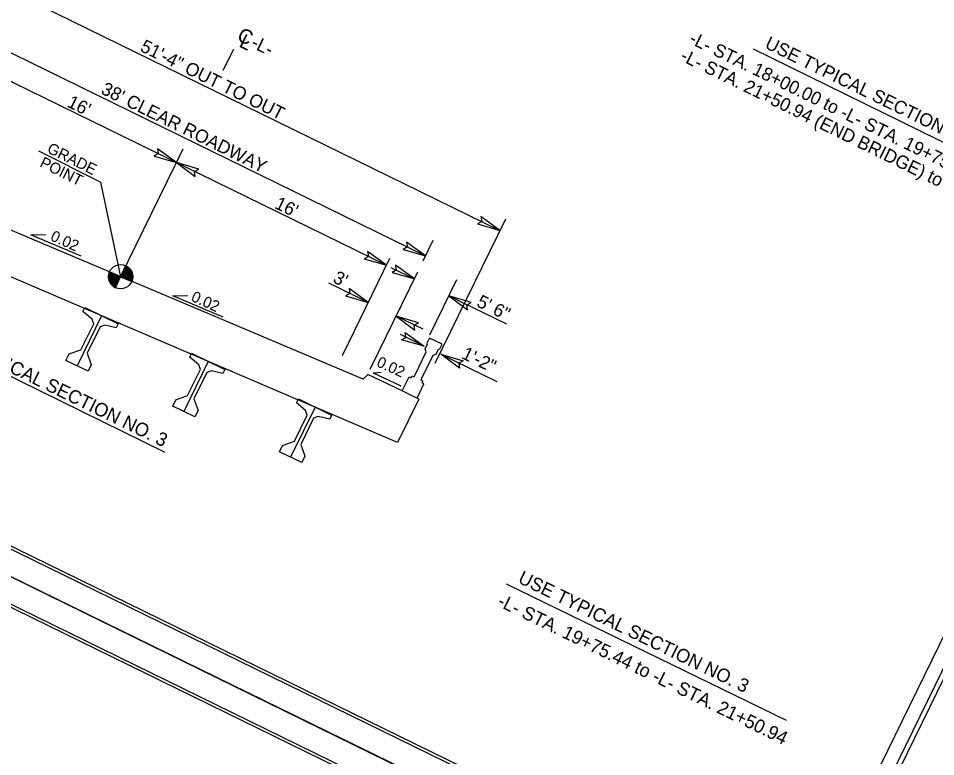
# Model space of a CAD drawing. Extents: x 1518247 to 1523638, y 635234 to 639927.
# Drawn here: x 1521243 to 1522074, y 637399 to 638068 of the extents above; entities that cross this region are included whole.
import ezdxf

# ---------------------------------------------------------------- set-up
doc = ezdxf.new("R2010")
doc.units = 0
for name, color, linetype in [('Default', 7, 'Continuous'), ('Default Symbol CELL', 7, 'Continuous'), ('Old_Level_1', 7, 'Continuous'), ('Prop Conc Barrier', 7, 'Continuous'), ('Prop Dimension', 7, 'Continuous'), ('Prop Dimension Text', 7, 'Continuous'), ('Sheet Cutting Line CELL', 7, 'Continuous'), ('Sheet Plot Border Inside CELL', 7, 'Continuous'), ('Sheet Plot Border Outside CELL', 7, 'Continuous'), ('Sheet Typical CELL', 7, 'Continuous'), ('Typical Arrow Superelevation CELL', 7, 'Continuous'), ('Typical Berm Information CELL', 7, 'Continuous'), ('Typical Pavement Slope CELL', 7, 'Continuous'), ('Typical Sidewalk and Rail CELL', 7, 'Continuous'), ('Typical Text Centerline CELL', 7, 'Continuous'), ('Typical Text Label CELL', 7, 'Continuous')]:
    doc.layers.add(name, color=color, linetype=linetype)

msp = doc.modelspace()

# ---------------------------------------------------------------- linework, layer by layer
at = {"layer": 'Default'}
for points in [[(1520441.97, 637950.34), (1521954.73, 637210.48), (1522438.02, 638198.63), (1520925.25, 638938.49)], [(1521471.45, 636222.33), (1519958.68, 636962.19), (1520441.97, 637950.34), (1521954.73, 637210.48)]]:
    msp.add_lwpolyline(points, close=True, dxfattribs=at)
at = {"layer": 'Default Symbol CELL'}
for p, q in [((1521301.17, 637802.23), (1521302.93, 637805.82)), ((1521302.93, 637805.82), (1521333.09, 637791.07)), ((1521318.01, 637798.44), (1521295.87, 637753.17)), ((1521309.46, 637795.51), (1521301.17, 637802.23)), ((1521299.32, 637767.51), (1521310.92, 637791.23)), ((1521316.67, 637788.42), (1521305.08, 637764.72)), ((1521310.92, 637791.23), (1521309.46, 637795.51)), ((1521320.95, 637789.89), (1521316.67, 637788.42)), ((1521331.34, 637787.48), (1521320.95, 637789.89)), ((1521333.09, 637791.07), (1521331.34, 637787.48)), ((1521285.82, 637758.09), (1521288.63, 637763.84)), ((1521288.63, 637763.84), (1521299.32, 637767.51)), ((1521305.07, 637764.7), (1521308.74, 637754)), ((1521397.94, 637760.86), (1521399.7, 637764.45)), ((1521399.7, 637764.45), (1521429.86, 637749.69)), ((1521305.93, 637748.26), (1521285.82, 637758.09)), ((1521414.78, 637757.07), (1521392.64, 637711.8)), ((1521406.22, 637754.14), (1521397.94, 637760.86)), ((1521308.74, 637754), (1521305.93, 637748.26)), ((1521396.09, 637726.14), (1521407.69, 637749.86)), ((1521413.44, 637747.05), (1521401.84, 637723.35)), ((1521407.69, 637749.86), (1521406.22, 637754.14)), ((1521417.71, 637748.52), (1521413.44, 637747.05)), ((1521428.1, 637746.1), (1521417.71, 637748.52)), ((1521429.86, 637749.69), (1521428.1, 637746.1)), ((1521382.58, 637716.72), (1521385.39, 637722.47)), ((1521385.39, 637722.47), (1521396.09, 637726.14)), ((1521401.83, 637723.33), (1521405.5, 637712.63)), ((1521494.71, 637719.48), (1521496.46, 637723.08)), ((1521496.46, 637723.08), (1521526.63, 637708.32)), ((1521402.69, 637706.89), (1521382.58, 637716.72)), ((1521511.55, 637715.7), (1521489.41, 637670.43)), ((1521502.99, 637712.76), (1521494.71, 637719.48)), ((1521405.5, 637712.63), (1521402.69, 637706.89)), ((1521492.86, 637684.76), (1521504.46, 637708.49)), ((1521510.2, 637705.68), (1521498.61, 637681.98)), ((1521504.46, 637708.49), (1521502.99, 637712.76)), ((1521514.48, 637707.14), (1521510.2, 637705.68)), ((1521524.87, 637704.73), (1521514.48, 637707.14)), ((1521526.63, 637708.32), (1521524.87, 637704.73)), ((1521479.35, 637675.35), (1521482.16, 637681.09)), ((1521482.16, 637681.09), (1521492.86, 637684.76)), ((1521498.6, 637681.95), (1521502.27, 637671.26)), ((1521499.46, 637665.51), (1521479.35, 637675.35)), ((1521502.27, 637671.26), (1521499.46, 637665.51))]:
    msp.add_line(p, q, dxfattribs=at)
at = {"layer": 'Old_Level_1'}
for p, q in [((1521437.59, 638039.67), (1521428.12, 638020.64)), ((1521316.96, 637919.46), (1521261.28, 637947.56)), ((1521335.32, 637833.84), (1521391.91, 637949.54)), ((1521555.19, 637741.09), (1521125.64, 637922.33)), ((1521316.96, 637919.46), (1521335.32, 637833.84)), ((1521586.4, 637683.7), (1521058.69, 637909.31)), ((1521253.86, 637871.76), (1521267.53, 637871.94)), ((1521299.57, 637852.39), (1521253.86, 637871.76)), ((1521325.28, 637838.3), (1521335.32, 637833.84)), ((1521335.32, 637833.84), (1521325.28, 637838.3)), ((1521339.81, 637843.88), (1521335.32, 637833.84)), ((1521330.84, 637823.81), (1521335.32, 637833.84)), ((1521335.32, 637833.84), (1521345.36, 637829.36)), ((1521382.68, 637816.63), (1521396.35, 637816.8)), ((1521428.39, 637797.25), (1521382.68, 637816.63))]:
    msp.add_line(p, q, dxfattribs=at)
for points in [[(1521365.61, 637943.16), (1521385.95, 637937.35), (1521368.67, 637949.78), (1521369.46, 637945.29)], [(1521406.21, 637931.28), (1521385.95, 637937.35), (1521403.06, 637924.7), (1521402.33, 637929.2)], [(1521658.8, 637881.6), (1521679.14, 637875.79), (1521661.86, 637888.22), (1521662.65, 637883.73)], [(1521591.38, 637858.62), (1521611.71, 637852.82), (1521594.43, 637865.25), (1521595.23, 637860.75)], [(1521556.05, 637850.02), (1521576.39, 637844.21), (1521559.11, 637856.64), (1521559.9, 637852.15)], [(1521581.4, 637837.62), (1521601.74, 637831.82), (1521584.45, 637844.25), (1521585.25, 637839.75)], [(1521539.31, 637816.39), (1521559.65, 637810.58), (1521542.37, 637823.01), (1521543.16, 637818.52)], [(1521653.06, 637810.55), (1521632.8, 637816.62), (1521649.91, 637803.96), (1521649.18, 637808.47)], [(1521605.25, 637792.11), (1521585, 637798.19), (1521602.11, 637785.53), (1521601.37, 637790.03)], [(1521593.23, 637783.2), (1521610.46, 637770.94), (1521589.96, 637776.68), (1521593.97, 637778.86)], [(1521642.55, 637751.11), (1521625.48, 637763.6), (1521645.9, 637757.59), (1521641.86, 637755.45)]]:
    msp.add_lwpolyline(points, close=True, dxfattribs=at)
for points in [[(1521335.25, 637833.69), (1521325.22, 637838.17), (1521325.22, 637838.17)], [(1521346.3, 637834.1), (1521337.25, 637838.15)], [(1521346.3, 637834.34), (1521337.34, 637838.35)], [(1521346.28, 637834.59), (1521337.43, 637838.55)], [(1521346.26, 637834.84), (1521337.52, 637838.75)], [(1521346.24, 637835.09), (1521337.61, 637838.95)], [(1521346.21, 637835.34), (1521337.69, 637839.15)], [(1521346.17, 637835.6), (1521337.78, 637839.35)], [(1521346.13, 637835.86), (1521337.87, 637839.55)], [(1521346.06, 637836.13), (1521337.96, 637839.75)], [(1521346.02, 637836.39), (1521338.05, 637839.95)], [(1521345.95, 637836.66), (1521338.14, 637840.15)], [(1521345.86, 637836.95), (1521338.23, 637840.35)], [(1521345.77, 637837.23), (1521338.32, 637840.55)], [(1521345.68, 637837.51), (1521338.41, 637840.75)], [(1521345.57, 637837.8), (1521338.5, 637840.96)], [(1521345.46, 637838.09), (1521338.59, 637841.16)], [(1521345.33, 637838.39), (1521338.68, 637841.36)], [(1521345.17, 637838.7), (1521338.77, 637841.56)], [(1521345.02, 637839.01), (1521338.86, 637841.76)], [(1521344.84, 637839.33), (1521338.95, 637841.96)], [(1521344.64, 637839.66), (1521339.04, 637842.16)], [(1521344.42, 637840), (1521339.13, 637842.36)], [(1521344.17, 637840.35), (1521339.22, 637842.56)], [(1521343.9, 637840.71), (1521339.31, 637842.76)], [(1521343.57, 637841.1), (1521339.4, 637842.96)], [(1521343.19, 637841.51), (1521339.49, 637843.16)], [(1521342.72, 637841.96), (1521339.58, 637843.36)], [(1521342.12, 637842.47), (1521339.67, 637843.57)], [(1521341.19, 637843.13), (1521339.76, 637843.77)], [(1521333.73, 637830.27), (1521324.34, 637834.47)], [(1521333.64, 637830.07), (1521324.34, 637834.23)], [(1521333.55, 637829.87), (1521324.34, 637833.99)], [(1521333.46, 637829.67), (1521324.34, 637833.75)], [(1521333.37, 637829.47), (1521324.34, 637833.51)], [(1521333.28, 637829.27), (1521324.34, 637833.27)], [(1521333.82, 637830.47), (1521324.36, 637834.7)], [(1521333.19, 637829.07), (1521324.36, 637833.02)], [(1521333.91, 637830.67), (1521324.38, 637834.93)], [(1521333.1, 637828.87), (1521324.38, 637832.76)], [(1521333.01, 637828.67), (1521324.4, 637832.51)], [(1521334, 637830.88), (1521324.41, 637835.16)], [(1521334.09, 637831.08), (1521324.45, 637835.38)], [(1521332.92, 637828.47), (1521324.45, 637832.25)], [(1521334.18, 637831.28), (1521324.48, 637835.61)], [(1521332.83, 637828.27), (1521324.49, 637831.99)], [(1521334.27, 637831.48), (1521324.52, 637835.83)], [(1521332.74, 637828.06), (1521324.53, 637831.73)], [(1521334.36, 637831.68), (1521324.57, 637836.05)], [(1521332.65, 637827.86), (1521324.58, 637831.47)], [(1521334.45, 637831.88), (1521324.61, 637836.27)], [(1521332.56, 637827.66), (1521324.65, 637831.2)], [(1521334.54, 637832.08), (1521324.66, 637836.49)], [(1521332.47, 637827.46), (1521324.71, 637830.93)], [(1521334.63, 637832.28), (1521324.72, 637836.71)], [(1521334.72, 637832.48), (1521324.77, 637836.93)], [(1521332.38, 637827.26), (1521324.8, 637830.65)], [(1521334.8, 637832.68), (1521324.84, 637837.14)], [(1521332.29, 637827.06), (1521324.89, 637830.37)], [(1521334.89, 637832.88), (1521324.9, 637837.35)], [(1521334.98, 637833.08), (1521324.97, 637837.56)], [(1521332.2, 637826.86), (1521324.98, 637830.09)], [(1521335.07, 637833.28), (1521325.06, 637837.76)], [(1521332.11, 637826.66), (1521325.09, 637829.8)], [(1521335.16, 637833.48), (1521325.13, 637837.97)], [(1521345.4, 637829.45), (1521345.4, 637829.45), (1521335.36, 637833.93)], [(1521345.49, 637829.65), (1521335.45, 637834.13)], [(1521345.56, 637829.86), (1521335.54, 637834.33)], [(1521345.65, 637830.06), (1521335.63, 637834.53)], [(1521345.71, 637830.27), (1521335.72, 637834.73)], [(1521345.78, 637830.48), (1521335.81, 637834.93)], [(1521345.85, 637830.69), (1521335.9, 637835.13)], [(1521345.91, 637830.9), (1521335.99, 637835.34)], [(1521345.98, 637831.11), (1521336.08, 637835.54)], [(1521346.03, 637831.33), (1521336.17, 637835.74)], [(1521346.07, 637831.55), (1521336.26, 637835.94)], [(1521346.12, 637831.77), (1521336.35, 637836.14)], [(1521346.16, 637831.99), (1521336.44, 637836.34)], [(1521346.19, 637832.22), (1521336.53, 637836.54)], [(1521346.23, 637832.45), (1521336.62, 637836.74)], [(1521346.25, 637832.68), (1521336.71, 637836.94)], [(1521346.28, 637832.91), (1521336.8, 637837.14)], [(1521346.3, 637833.14), (1521336.89, 637837.34)], [(1521346.3, 637833.38), (1521336.98, 637837.54)], [(1521346.3, 637833.62), (1521337.07, 637837.74)], [(1521346.3, 637833.86), (1521337.16, 637837.94)], [(1521332.02, 637826.46), (1521325.22, 637829.5)], [(1521331.93, 637826.26), (1521325.36, 637829.2)], [(1521331.84, 637826.06), (1521325.51, 637828.89)], [(1521331.76, 637825.86), (1521325.67, 637828.58)], [(1521331.67, 637825.66), (1521325.84, 637828.26)], [(1521331.58, 637825.46), (1521326.05, 637827.93)], [(1521331.49, 637825.26), (1521326.27, 637827.59)], [(1521331.4, 637825.05), (1521326.53, 637827.23)], [(1521331.31, 637824.85), (1521326.82, 637826.86)], [(1521331.22, 637824.65), (1521327.16, 637826.47)], [(1521331.13, 637824.45), (1521327.54, 637826.06)], [(1521331.04, 637824.25), (1521328.05, 637825.59)], [(1521330.95, 637824.05), (1521328.67, 637825.07)], [(1521330.86, 637823.85), (1521329.77, 637824.34)]]:
    msp.add_lwpolyline(points, dxfattribs=at)
msp.add_circle((1521335.32, 637833.83), 10.99, dxfattribs=at)
for start, end in [(155.93113, 245.93113), (335.93113, 65.93113)]:
    msp.add_arc((1521335.32, 637833.83), 10.99, start, end, dxfattribs=at)
at = {"layer": 'Prop Conc Barrier'}
for p, q in [((1521611.47, 637768.55), (1521613.65, 637773.01)), ((1521613.14, 637774), (1521615.25, 637778.3)), ((1521613.65, 637773.01), (1521613.14, 637774)), ((1521626.74, 637772.68), (1521615.25, 637778.3)), ((1521624.63, 637768.38), (1521626.74, 637772.68)), ((1521602.24, 637745.08), (1521612.44, 637765.94)), ((1521612.44, 637765.94), (1521611.47, 637768.55)), ((1521618.72, 637762.9), (1521621.34, 637763.72)), ((1521621.34, 637763.72), (1521623.51, 637768.17)), ((1521623.51, 637768.17), (1521624.63, 637768.38)), ((1521608.51, 637742.02), (1521618.72, 637762.9)), ((1521590.63, 637730.4), (1521596.92, 637743.26)), ((1521596.92, 637743.26), (1521598.71, 637742.39)), ((1521598.71, 637742.39), (1521599.58, 637744.17)), ((1521599.58, 637744.17), (1521601.37, 637743.3)), ((1521601.37, 637743.3), (1521602.24, 637745.08)), ((1521607.63, 637740.23), (1521608.51, 637742.02)), ((1521609.42, 637739.36), (1521607.63, 637740.23)), ((1521608.54, 637737.58), (1521609.42, 637739.36)), ((1521605.65, 637723.06), (1521590.63, 637730.4)), ((1521604.04, 637723.85), (1521610.33, 637736.7)), ((1521610.33, 637736.7), (1521608.54, 637737.58))]:
    msp.add_line(p, q, dxfattribs=at)
at = {"layer": 'Prop Dimension'}
for p, q in [((1521165.23, 638127.14), (1521679.14, 637875.79)), ((1521189.36, 638059.38), (1521611.71, 637852.82)), ((1521204.65, 638026.02), (1521576.23, 637844.29)), ((1521684.12, 637885.96), (1521620.18, 637755.24)), ((1521609.46, 637848.21), (1521618.67, 637867.04)), ((1521536.38, 637762.39), (1521579.49, 637850.55)), ((1521561.48, 637750.11), (1521604.6, 637838.27)), ((1521580.4, 637842.25), (1521601.74, 637831.82)), ((1521639.89, 637831.11), (1521615.32, 637780.87)), ((1521559.89, 637810.47), (1521524.16, 637827.94)), ((1521632.8, 637816.62), (1521685, 637791.09)), ((1521609.53, 637786.19), (1521585, 637798.19)), ((1521610.46, 637770.94), (1521589.18, 637781.35)), ((1521625.48, 637763.6), (1521676.22, 637738.78))]:
    msp.add_line(p, q, dxfattribs=at)
at = {"layer": 'Sheet Cutting Line CELL'}
for p, q in [((1520441.97, 637950.34), (1521954.73, 637210.48)), ((1521954.73, 637210.48), (1520441.97, 637950.34))]:
    msp.add_line(p, q, dxfattribs=at)
at = {"layer": 'Sheet Plot Border Inside CELL'}
for points in [[(1522424.11, 638180.44), (1520927.06, 638912.61), (1520463.51, 637964.8), (1521960.55, 637232.62)], [(1521940.83, 637192.29), (1520443.78, 637924.46), (1519980.23, 636976.65), (1521477.27, 636244.48)]]:
    msp.add_lwpolyline(points, close=True, dxfattribs=at)
at = {"layer": 'Sheet Plot Border Outside CELL'}
for points in [[(1522438.02, 638198.63), (1520925.25, 638938.49), (1520441.97, 637950.34), (1521954.73, 637210.48)], [(1521954.73, 637210.48), (1520441.97, 637950.34), (1519958.68, 636962.19), (1521471.45, 636222.33)]]:
    msp.add_lwpolyline(points, close=True, dxfattribs=at)
at = {"layer": 'Sheet Typical CELL'}
for points in [[(1522411.76, 638183.64), (1521064.29, 638842.66), (1520602.97, 637899.43), (1521950.45, 637240.41)], [(1521928.48, 637195.49), (1520581, 637854.51), (1520119.69, 636911.28), (1521467.16, 636252.26)]]:
    msp.add_lwpolyline(points, close=True, dxfattribs=at)
at = {"layer": 'Typical Arrow Superelevation CELL'}
msp.add_line((1521564.26, 637746.8), (1521571.52, 637747.44), dxfattribs=at)
at = {"layer": 'Typical Berm Information CELL'}
msp.add_line((1521564.26, 637746.8), (1521589.44, 637735.1), dxfattribs=at)
at = {"layer": 'Typical Sidewalk and Rail CELL'}
for p, q in [((1521555.19, 637741.09), (1521559.31, 637745.38)), ((1521590.63, 637730.4), (1521559.31, 637745.38)), ((1521605.65, 637723.06), (1521586.4, 637683.7))]:
    msp.add_line(p, q, dxfattribs=at)
at = {"layer": 'Typical Text Label CELL'}
for p, q in [((1521908.73, 638040.14), (1522156.85, 637918.56)), ((1521193.4, 637764.17), (1521375.3, 637675.05)), ((1521684.76, 637555.82), (1521938.76, 637432.21))]:
    msp.add_line(p, q, dxfattribs=at)

# ---------------------------------------------------------------- texts
at = {"layer": 'Old_Level_1'}
for s, height, rotation, p in [('GRADE', 10.005, 333.53399, (1521267.9, 637946.81)), ('POINT', 10.005, 333.53399, (1521261.25, 637933.97)), ('0.02', 9.969, 335.9216, (1521271.02, 637867.09)), ('0.02', 9.969, 335.9216, (1521398.51, 637812.18))]:
    msp.add_text(s, height=height, rotation=rotation, dxfattribs=at).set_placement(p)
at = {"layer": 'Prop Dimension'}
for s, height, rotation, p in [('51\'-4" OUT TO OUT', 11.8652, 333.74084, (1521352.24, 638038.61)), ("38' CLEAR ROADWAY", 11.8652, 333.74084, (1521316.71, 638000.12)), ("16'", 11.865, 333.74084, (1521286.02, 637988.23)), ("16'", 11.865, 334.13461, (1521474.1, 637896.28)), ("3'", 11.865, 333.74084, (1521526.96, 637829.17)), ('5\' 6"', 11.865, 333.74084, (1521657.18, 637807.4)), ('1\'-2"', 11.865, 334.13461, (1521643.55, 637760.29))]:
    msp.add_text(s, height=height, rotation=rotation, dxfattribs=at).set_placement(p)
at = {"layer": 'Prop Dimension Text'}
for s, height, rotation, p in [('-L-', 11.962, 333.89618, (1521452.71, 638042.12)), ('TYPICAL SECTION NO. 3', 12.2298, 334.0511, (1521200.84, 637763.56))]:
    msp.add_text(s, height=height, rotation=rotation, dxfattribs=at).set_placement(p)
at = {"layer": 'Typical Berm Information CELL'}
msp.add_text('0.02', height=9.969, rotation=335.7046, dxfattribs=at).set_placement((1521566.58, 637752.97))
at = {"layer": 'Typical Pavement Slope CELL'}
for s, height, rotation, p in [('-L- STA. 18+00.00 to -L- STA. 19+75.44 (BEG. BRIDGE)', 11.8983, 333.89618, (1521849.83, 638045.79)), ('-L- STA. 21+50.94 (END BRIDGE) to -L- STA. 23+50.00', 11.8983, 333.89618, (1521841.84, 638030.18)), ('-L- STA. 19+75.44 to -L- STA. 21+50.94', 12.1642, 334.0511, (1521676.03, 637536.14))]:
    msp.add_text(s, height=height, rotation=rotation, dxfattribs=at).set_placement(p)
at = {"layer": 'Typical Text Centerline CELL'}
for s, height, rotation, p in [('C', 13.08, 333.89618, (1521439.94, 638048.45)), ('L', 13.09, 333.84308, (1521441.88, 638042.52))]:
    msp.add_text(s, height=height, rotation=rotation, dxfattribs=at).set_placement(p)
at = {"layer": 'Typical Text Label CELL'}
for s, height, rotation, p in [('USE TYPICAL SECTION NO. 2', 11.8983, 333.89618, (1521918.44, 638041.39)), ('USE TYPICAL SECTION NO. 3', 12.1642, 334.0511, (1521694.68, 637557.12))]:
    msp.add_text(s, height=height, rotation=rotation, dxfattribs=at).set_placement(p)

doc.saveas('drawing.dxf')
